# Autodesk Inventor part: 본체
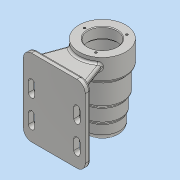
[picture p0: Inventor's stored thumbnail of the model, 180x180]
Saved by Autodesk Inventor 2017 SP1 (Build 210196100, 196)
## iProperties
Part Number: 본체
Material: 알루미늄 6061
Document SubType Name: Modeling
Designer: MRC
Density: 2.7 g/cm^3
Appearance: 알루미늄 - 평지
Mass: 694.197 g
Surface Area: 698.877 cm^2
Volume: 257.11 cm^3
Author: MRC
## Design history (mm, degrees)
sketch "스케치1"
  geometry: C1 r 34 at (0, 0); 1 further point
  constraints: 1 centre point, 1 coincident
  dimensions: "d0" = 68 diameter of C1
extrude "돌출1" new body sketch "스케치1" distance "d1" = 32; taper "d2" = 0 deg
sketch "스케치2"
  geometry: C1 r 34 at (0, 0) reference; C2 r 30 at (0, 0)
  constraints: 1 centre point, 1 coincident
  dimensions: "d3" = 60 diameter of C2
extrude "돌출2" join sketch "스케치2" distance "d4" = 34; taper "d5" = 0 deg
sketch "스케치3"
  geometry: C1 r 30 at (0, 0) reference; C2 r 27 at (0, 0)
  constraints: 1 centre point, 1 coincident
  dimensions: "d6" = 54 diameter of C2
extrude "돌출3" join sketch "스케치3" distance "d7" = 22; taper "d8" = 0 deg
sketch "스케치4"
  geometry: C1 r 27 at (0, 0) reference; C2 r 25 at (0, 0)
  constraints: 1 centre point, 1 coincident
  dimensions: "d110" = 50 diameter of C2
extrude "돌출4" join sketch "스케치4" distance "d9" = 24; taper "d10" = 0 deg
sketch "스케치5"
  geometry: C1 r 34 at (0, 0) reference; C2 r 21 at (0, 0)
  constraints: 1 centre point, 1 coincident
  dimensions: "d11" = 42 diameter of C2
extrude "돌출5" cut sketch "스케치5" distance "d12" = 15; taper "d13" = 0 deg
sketch "스케치6"
  geometry: C1 r 21 at (0, 0) reference; C2 r 24 at (0, 0)
  constraints: 1 centre point, 1 coincident
  dimensions: "d14" = 48 diameter of C2
extrude "돌출6" cut sketch "스케치6" distance "d15" = 54; taper "d16" = 0 deg
sketch "스케치7"
  geometry: C1 r 24 at (0, 0) reference; C2 r 21 at (0, 0)
  constraints: 1 centre point, 1 coincident
  dimensions: "d17" = 42 diameter of C2
extrude "돌출7" cut sketch "스케치7" distance "d18" = 12; taper "d19" = 0 deg
sketch "스케치8"
  geometry: C1 r 21 at (0, 0) reference; C2 r 17.5 at (0, 0)
  constraints: 1 centre point, 1 coincident
  dimensions: "d20" = 35 diameter of C2
extrude "돌출8" cut sketch "스케치8" distance "d21" = 18; taper "d22" = 0 deg
sketch "스케치9"
  geometry: C1 r 17.5 at (0, 0) reference; C2 r 16 at (0, 0)
  constraints: 1 centre point, 1 coincident
  dimensions: "d23" = 32 diameter of C2
extrude "돌출9" cut sketch "스케치9" distance "d24" = 4; taper "d25" = 0 deg
sketch "스케치10"
  geometry: C1 r 16 at (0, 0) reference; C2 r 10.5 at (0, 0)
  constraints: 1 centre point, 1 coincident
  dimensions: "d26" = 21 diameter of C2
extrude "돌출11" cut sketch "스케치10" distance "d29" = 3; taper "d30" = 0 deg
fillet "모깎기1" dims "d31" = 0.3
fillet "모깎기2" dims "d32" = 3
fillet "모깎기3" dims "d33" = 0.3
fillet "모깎기4" dims "d34" = 3
chamfer "모따기1" distance "d35" = 1; stored, may be unused: second distance "d36" = 2, angle "d37" = 45 deg
fillet "모깎기10" dims "d111" = 3
node "작업 평면1"
sketch "스케치11"
  geometry: L1 (-45, -112)-(45, -112); L2 (45, -112)-(45, 0); L3 (45, 0)-(-45, 0); L4 (-45, 0)-(-45, -112); 2 further points
  constraints: 8 end point, 2 parallel, 1 coincident, 1 horizontal, 1 midpoint, 1 perpendicular
  dimensions: "d39" = 90 distance of L3.end L2.end; "d40" = 112 distance of L2.end L1.end
extrude "돌출12" join sketch "스케치11" distance "d41" = 8; taper "d42" = 0 deg
node "작업 평면2"
sketch "스케치17"
  geometry: L1 (45, 112)-(-45, 112) reference; L2 (-45, 0)-(45, 0) reference; L3 (4, 85)-(-4, 85); L4 (-4, 85)-(-4, 8); L5 (-4, 8)-(4, 8); L6 (4, 8)-(4, 85); 3 further points
  constraints: 8 end point, 2 midpoint, 2 parallel, 1 horizontal, 1 perpendicular, 1 vertical alignment
  dimensions: "d55" = 8 distance of L3.start L3.end; "d56" = 77 distance of L5.end L3.start; "d57" = 8 distance between parallel lines of L2 L5
extrude "돌출13" join sketch "스케치17" stored distance "d58" = 8; taper "d59" = 0 deg
sketch "스케치18"
  geometry: L1 (-41, -8)-(-41, 0) reference; L2 (-41, 0)-(0, 0) reference; L3 (0, 0)-(0, 28.236) reference; L4 (8, 28.236)-(8, 0) reference; L5 (8, 0)-(49, 0) reference; L6 (49, 0)-(49, -8) reference; L7 (49, -8)-(-41, -8) reference; L8 (0, 0)-(8, 0) reference; L9 (-19.409, 37.342)-(-33, 0); C1 r 21 at (4, 62) reference; A1 r 34 centre (4, 62) between (0, 28.236) and (8, 28.236) reference; A2 r 34 centre (4, 62) between (8, 28.236) and (0, 28.236) reference
  constraints: 2 end point, 1 point on circle, 1 point on line
  dimensions: "d60" = 20 deg angle of L1 L9; "d61" = 8 distance from line of L1 L9.end
extrude "돌출14" join sketch "스케치18" distance "d62" = 8; taper "d63" = 0 deg
feature "면 기울기1" dims angle "d64" = 15 deg
fillet "모깎기5" dims "d65" = 3
fillet "모깎기6" dims "d66" = 12
sketch "스케치19"
  geometry: L1 (33, 112)-(-33, 112) reference; L2 (33, 92)-(33, 77); L3 (28.5, 92)-(28.5, 77); L4 (37.5, 77)-(37.5, 92); L5 (33, 52)-(33, 37); L6 (28.5, 52)-(28.5, 37); L7 (37.5, 37)-(37.5, 52); L8 (33, 0)-(-33, 0) reference; L9 (-45, 12)-(-45, 100) reference; L10 (-33, 112)-(33, 112) reference; L11 (45, 100)-(45, 12) reference; L12 (4, 81.894)-(4, 19) reference; L13 (7, 16)-(33.807, 16) reference; L14 (37, 13)-(37, 11) reference; L15 (33.807, 8)-(-33.807, 8) reference; L16 (-37, 11)-(-37, 13) reference; L17 (-33.807, 16)-(-7, 16) reference; L18 (-4, 19)-(-4, 81.894) reference; L19 (-1, 85)-(1, 85) reference; L20 (-33, 92)-(-33, 77); L21 (-37.5, 92)-(-37.5, 77); L22 (-28.5, 77)-(-28.5, 92); L23 (-33, 52)-(-33, 37); L24 (-37.5, 52)-(-37.5, 37); L25 (-28.5, 37)-(-28.5, 52); A1 r 4.5 centre (33, 92) between (37.5, 92) and (28.5, 92); A2 r 4.5 centre (33, 77) between (28.5, 77) and (37.5, 77); A3 r 4.5 centre (33, 52) between (37.5, 52) and (28.5, 52); A4 r 4.5 centre (33, 37) between (28.5, 37) and (37.5, 37); A5 r 12 centre (33, 12) between (33, 0) and (45, 12) reference; A6 r 12 centre (-33, 12) between (-45, 12) and (-33, 0) reference; A7 r 12 centre (-33, 100) between (-33, 112) and (-45, 100) reference; A8 r 12 centre (33, 100) between (45, 100) and (33, 112) reference; A9 r 3 centre (7, 19) between (4, 19) and (7, 16) reference; A10 r 3 centre (-7, 19) between (-7, 16) and (-4, 19) reference; A11 r 4.5 centre (-33, 92) between (-28.5, 92) and (-37.5, 92); A12 r 4.5 centre (-33, 77) between (-37.5, 77) and (-28.5, 77); A13 r 4.5 centre (-33, 52) between (-28.5, 52) and (-37.5, 52); A14 r 4.5 centre (-33, 37) between (-37.5, 37) and (-28.5, 37); 11 further points; 6 other entities
  constraints: 32 end point, 16 point on circle, 16 tangent, 8 centre point, 5 parallel, 4 midpoint, 3 vertical, 6 other
  dimensions: "d67" = 15 distance of L2.start L2.end; "d68" = 9 diameter of A2; "d69" = 15 distance of L5.start L5.end; "d70" = 9 diameter of A4; "d71" = 25 distance of L5.start L2.end; "d73" = 33 horizontal distance of point (0, 0) point (33, 84.5); "d74" = 15 distance of L20.start L20.end; "d75" = 9 diameter of A12; "d76" = 15 distance of L23.start L23.end; "d77" = 9 diameter of A14; "d78" = 33 horizontal distance of point (0, 0) point (33, 44.5); "d79" = 33 horizontal distance of point (0, 0) point (-33, 44.5); "d80" = 33 horizontal distance of point (0, 0) point (-33, 84.5); "d82" = 25 distance of L23.start L20.end; "d85" = 20 distance from line of L20.start L1; "d86" = 20 distance from line of L1 L2.start
extrude "돌출15" cut sketch "스케치19" distance "d87" = 8; taper "d88" = 0 deg
fillet "모깎기7" dims "d89" = 3
fillet "모깎기8" dims "d90" = 8
sketch "스케치20"
  geometry: L1 (33, 112)-(-33, 112) reference; A1 r 4.5 centre (33, 92) between (37.5, 92) and (28.5, 92) reference; 2 further points
  constraints: 1 other
  dimensions: "d92" = 33 horizontal distance of A1.centre point (0, 100); "d93" = 12 distance from line of L1 point (0, 100)
feature "엠보싱1" sketch "스케치20" dims "d0" = 68, "d94" = 0.5, "d95" = 0
sketch "스케치21" dims "d98" = 52
  geometry: C1 r 34 at (0, 0) reference; C2 r 22 at (0, 0) reference; 4 further points
  constraints: 1 coincident, 1 horizontal alignment, 6 other
  dimensions: "d101" = 360 deg dimension on C1.centre point (-26, 0) (derived)
hole "구멍1" sketch "스케치21" at (13, 22.517), (13, -22.517), (-26, 0) diameter "d103" = 3.242; stored, may be unused: countersink angle "d107" = 90 deg, drill point angle "d109" = 118 deg; dims "d104" = 8, "d105" = 4, "d106" = 2, "d108" = 11
fillet "모깎기11" dims "d112" = 3
node "솔리드1"
mirror "미러1"
node "절단 모서리 투영1"
node "절단 모서리 투영2"
other parameters: "d46" = -12
